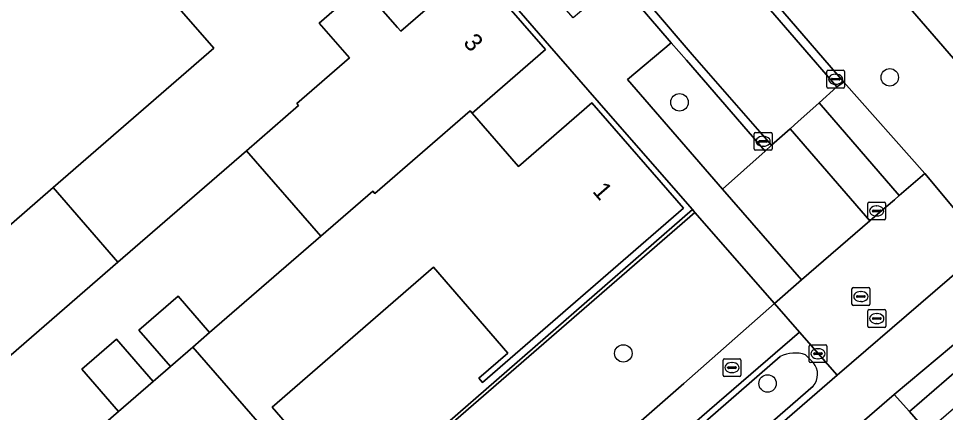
# Model space of a CAD drawing. Extents: x 155887 to 156869, y 383880 to 384678.
# Drawn here: x 156224 to 156276, y 384085.6 to 384107.7 of the extents above; entities that cross this region are included whole.
import ezdxf

# ---------------------------------------------------------------- set-up
doc = ezdxf.new("R2010")
doc.units = 0
for name, color, linetype in [('IMGEO_Berm_groen', 7, 'Continuous'), ('IMGEO_Boom', 7, 'Continuous'), ('IMGEO_Erf', 7, 'Continuous'), ('IMGEO_Fietspad_gesloten', 7, 'Continuous'), ('IMGEO_Greppel_droge_sloot', 7, 'Continuous'), ('IMGEO_Groenvoorziening', 7, 'Continuous'), ('IMGEO_Haag', 7, 'Continuous'), ('IMGEO_Kolk', 7, 'Continuous'), ('IMGEO_Pand', 7, 'Continuous'), ('IMGEO_Pand_nummerreeks', 7, 'Continuous'), ('IMGEO_Rijbaan_lokaal_gesloten', 7, 'Continuous'), ('IMGEO_Rijbaan_lokaal_open', 7, 'Continuous'), ('IMGEO_Rioolput', 7, 'Continuous'), ('IMGEO_Voetpad_open', 7, 'Continuous')]:
    doc.layers.add(name, color=color, linetype=linetype)

msp = doc.modelspace()

# ---------------------------------------------------------------- linework, layer by layer
at = {"layer": 'IMGEO_Berm_groen'}
for points in [[(156240.218, 384147.268), (156236.004, 384143.601), (156236.378, 384143.165), (156259.369, 384116.661), (156259.86, 384116.097), (156266.847, 384108.071), (156270.265, 384104.121), (156274.816, 384099.002), (156277.067, 384096.295), (156281.229, 384099.923), (156277.633, 384104.037), (156267.33, 384115.942)], [(156261.455, 384105.344), (156260.59, 384106.325), (156258.145, 384104.257), (156263.479, 384098.12), (156265.865, 384100.248)], [(156270.265, 384104.121), (156269.874, 384103.844), (156268.884, 384102.961), (156273.38, 384097.76), (156274.816, 384099.002)], [(156267.255, 384101.508), (156266.212, 384100.578), (156265.865, 384100.248), (156263.479, 384098.12), (156267.907, 384093.026), (156271.731, 384096.334)], [(156267.782, 384090.109), (156262.74, 384085.745), (156228.231, 384055.73), (156230.294, 384053.373), (156269.896, 384087.691)]]:
    msp.add_lwpolyline(points, close=True, dxfattribs=at)
for points in [[(156229.652, 384056.467), (156266.709, 384088.74)], [(156268.123, 384088.828), (156268.567, 384088.388)], [(156268.552, 384087.083), (156231.611, 384054.962)]]:
    msp.add_lwpolyline(points, dxfattribs=at)
for centre, radius, start, end in [((156267.519, 384087.133), 1.8, 70.3811, 116.7413), ((156267.799, 384087.744), 1.002, 318.7214, 39.9615)]:
    msp.add_arc(centre, radius, start, end, dxfattribs=at)
at = {"layer": 'IMGEO_Boom'}
for centre in [(156272.845, 384104.384), (156261.061, 384102.983), (156257.913, 384088.912), (156265.996, 384087.225)]:
    msp.add_circle(centre, 0.489, dxfattribs=at)
at = {"layer": 'IMGEO_Erf'}
for points in [[(156233.788, 384073.174), (156236.052, 384075.143), (156235.843, 384075.385), (156236.084, 384075.595), (156236.293, 384075.353), (156236.363, 384075.42), (156236.657, 384075.088), (156237.409, 384075.743), (156244.556, 384081.969), (156245.305, 384082.622), (156261.783, 384096.974), (156257.057, 384102.381), (156253.783, 384106.157), (156249.606, 384110.968), (156241.618, 384120.183), (156237.428, 384125.007), (156235.411, 384127.346), (156228.952, 384134.784), (156195.288, 384105.561), (156189.338, 384100.396), (156193.713, 384095.326), (156201.684, 384086.153), (156205.864, 384081.345), (156221.93, 384062.847)], [(156234.965, 384106.021), (156230.69, 384110.939), (156231.808, 384111.909), (156231.69, 384112.045), (156229.307, 384114.791), (156227.527, 384116.842), (156217.399, 384108.054), (156208.415, 384100.257), (156212.696, 384095.324), (156212.814, 384095.188), (156211.705, 384094.224), (156215.875, 384089.428), (156225.97, 384098.203)], [(156236.789, 384100.268), (156229.588, 384094.022), (156220.6, 384086.227), (156224.76, 384081.431), (156229.628, 384085.654), (156227.569, 384088.028), (156229.513, 384089.714), (156231.573, 384087.341), (156232.538, 384088.178), (156230.767, 384090.219), (156232.958, 384092.12), (156234.729, 384090.078), (156240.961, 384095.484)]]:
    msp.add_lwpolyline(points, close=True, dxfattribs=at)
msp.add_lwpolyline([(156243.249, 384109.497), (156245.253, 384107.188), (156245.439, 384106.973), (156249.554, 384110.547), (156253.551, 384105.953), (156249.439, 384102.376), (156252.039, 384099.387), (156256.151, 384102.964), (156261.293, 384097.054), (156250.026, 384087.273), (156249.817, 384087.515), (156251.448, 384088.93), (156247.275, 384093.741), (156238.225, 384085.892), (156239.798, 384084.078)], dxfattribs=at)
at = {"layer": 'IMGEO_Fietspad_gesloten'}
for points in [[(156321.213, 384132.469), (156314.047, 384125.913), (156291.359, 384106.231), (156284.254, 384100.056), (156283.954, 384099.797), (156269.896, 384087.691), (156230.294, 384053.373), (156228.715, 384051.972), (156223.252, 384047.246), (156221.532, 384045.745), (156182.003, 384011.384), (156180.455, 384010.006), (156174.916, 384005.204), (156173.353, 384003.808), (156169.034, 384000), (156168.573, 383999.541)], [(156225.091, 384044.821), (156232.142, 384050.972), (156265.486, 384080.026), (156271.299, 384085.055), (156273.092, 384086.615), (156283.541, 384095.347), (156286.027, 384097.441), (156286.341, 384097.706), (156304.975, 384114.033), (156305.378, 384113.591), (156305.662, 384113.279), (156306.714, 384114.217), (156306.4, 384114.594), (156306.05, 384115.013), (156315.997, 384123.54), (156323.254, 384130.15), (156323.467, 384130.447)]]:
    msp.add_lwpolyline(points, dxfattribs=at)
at = {"layer": 'IMGEO_Greppel_droge_sloot'}
for points in [[(156266.709, 384088.74), (156229.652, 384056.467)], [(156268.567, 384088.388), (156268.123, 384088.828)], [(156231.611, 384054.962), (156268.552, 384087.083)]]:
    msp.add_lwpolyline(points, dxfattribs=at)
for centre, radius, start, end in [((156267.519, 384087.133), 1.8, 70.3811, 116.7413), ((156267.799, 384087.744), 1.002, 318.7214, 39.9615)]:
    msp.add_arc(centre, radius, start, end, dxfattribs=at)
at = {"layer": 'IMGEO_Groenvoorziening'}
for points in [[(156245.422, 384082.489), (156261.927, 384096.809), (156261.783, 384096.974), (156245.305, 384082.622)], [(156249.95, 384077.285), (156261.303, 384087.219), (156266.381, 384091.712), (156261.927, 384096.809), (156245.422, 384082.489)], [(156280.05, 384090.968), (156280.427, 384091.296), (156284.205, 384094.584), (156283.541, 384095.347), (156273.092, 384086.615), (156273.953, 384085.664), (156276.712, 384088.043)]]:
    msp.add_lwpolyline(points, close=True, dxfattribs=at)
at = {"layer": 'IMGEO_Haag'}
for points in [[(156245.422, 384082.489), (156261.927, 384096.809), (156261.783, 384096.974), (156245.305, 384082.622)], [(156273.092, 384086.615), (156273.953, 384085.664), (156276.712, 384088.043), (156280.05, 384090.968), (156280.427, 384091.296), (156284.205, 384094.584), (156283.541, 384095.347)]]:
    msp.add_lwpolyline(points, close=True, dxfattribs=at)
at = {"layer": 'IMGEO_Kolk'}
for p, q in [((156269.312, 384103.855), (156269.312, 384104.707)), ((156269.387, 384104.781), (156270.239, 384104.781)), ((156269.614, 384104.324), (156270.012, 384104.324)), ((156269.8, 384104.561), (156269.825, 384104.561)), ((156270.313, 384104.707), (156270.313, 384103.855)), ((156269.571, 384104.275), (156269.571, 384104.287)), ((156270.009, 384104.238), (156269.611, 384104.238)), ((156269.823, 384104.001), (156269.798, 384104.001)), ((156270.055, 384104.287), (156270.055, 384104.275)), ((156270.239, 384103.781), (156269.387, 384103.781)), ((156265.247, 384100.374), (156265.247, 384101.226)), ((156265.322, 384101.3), (156266.174, 384101.3)), ((156266.248, 384101.226), (156266.248, 384100.374)), ((156265.506, 384100.794), (156265.506, 384100.806)), ((156265.944, 384100.757), (156265.546, 384100.757)), ((156265.549, 384100.843), (156265.947, 384100.843)), ((156265.735, 384101.08), (156265.76, 384101.08)), ((156265.99, 384100.806), (156265.99, 384100.794)), ((156266.174, 384100.3), (156265.322, 384100.3)), ((156265.758, 384100.52), (156265.733, 384100.52)), ((156268.322, 384088.467), (156268.322, 384089.319)), ((156268.397, 384089.393), (156269.249, 384089.393)), ((156269.323, 384089.319), (156269.323, 384088.467)), ((156268.581, 384088.887), (156268.581, 384088.899)), ((156269.019, 384088.85), (156268.621, 384088.85)), ((156268.624, 384088.936), (156269.022, 384088.936)), ((156268.81, 384089.173), (156268.835, 384089.173)), ((156269.065, 384088.899), (156269.065, 384088.887)), ((156269.249, 384088.393), (156268.397, 384088.393)), ((156268.833, 384088.613), (156268.808, 384088.613))]:
    msp.add_line(p, q, dxfattribs=at)
for points in [[(156269.312, 384103.855), (156269.312, 384104.707)], [(156269.387, 384104.781), (156270.239, 384104.781)], [(156270.313, 384104.707), (156270.313, 384103.855)], [(156270.239, 384103.781), (156269.387, 384103.781)], [(156265.247, 384100.374), (156265.247, 384101.226)], [(156265.322, 384101.3), (156266.174, 384101.3)], [(156266.248, 384101.226), (156266.248, 384100.374)], [(156266.174, 384100.3), (156265.322, 384100.3)], [(156268.322, 384088.467), (156268.322, 384089.319)], [(156268.397, 384089.393), (156269.249, 384089.393)], [(156269.323, 384089.319), (156269.323, 384088.467)], [(156269.249, 384088.393), (156268.397, 384088.393)]]:
    msp.add_lwpolyline(points, dxfattribs=at)
for centre, radius, start, end in [((156269.389, 384104.705), 0.0765, 91.552, 178.448), ((156269.389, 384104.705), 0.0765, 91.552, 178.448), ((156269.611, 384104.284), 0.0403, 85.8775, 175.7526), ((156270.016, 384104.286), 0.0386, 1.7309, 96.639), ((156270.237, 384104.705), 0.0765, 1.552, 88.448), ((156270.237, 384104.705), 0.0765, 1.552, 88.448), ((156269.389, 384103.857), 0.0765, 181.552, 268.448), ((156269.389, 384103.857), 0.0765, 181.552, 268.448), ((156269.608, 384104.274), 0.0366, 178.938, 274.7102), ((156270.012, 384104.281), 0.043, 264.8664, 352.4533), ((156270.237, 384103.857), 0.0765, 271.552, 358.448), ((156270.237, 384103.857), 0.0765, 271.552, 358.448), ((156265.324, 384101.224), 0.0765, 91.552, 178.448), ((156265.324, 384101.224), 0.0765, 91.552, 178.448), ((156266.172, 384101.224), 0.0765, 1.552, 88.448), ((156266.172, 384101.224), 0.0765, 1.552, 88.448), ((156265.546, 384100.803), 0.0403, 85.8775, 175.7526), ((156265.543, 384100.793), 0.0366, 178.938, 274.7102), ((156265.947, 384100.8), 0.043, 264.8664, 352.4533), ((156265.951, 384100.805), 0.0386, 1.7309, 96.639), ((156265.324, 384100.376), 0.0765, 181.552, 268.448), ((156265.324, 384100.376), 0.0765, 181.552, 268.448), ((156266.172, 384100.376), 0.0765, 271.552, 358.448), ((156266.172, 384100.376), 0.0765, 271.552, 358.448), ((156268.399, 384089.317), 0.0765, 91.552, 178.448), ((156268.399, 384089.317), 0.0765, 91.552, 178.448), ((156269.247, 384089.317), 0.0765, 1.552, 88.448), ((156269.247, 384089.317), 0.0765, 1.552, 88.448), ((156268.621, 384088.896), 0.0403, 85.8775, 175.7526), ((156268.618, 384088.886), 0.0366, 178.938, 274.7102), ((156269.022, 384088.893), 0.043, 264.8664, 352.4533), ((156269.026, 384088.898), 0.0386, 1.7309, 96.639), ((156268.399, 384088.469), 0.0765, 181.552, 268.448), ((156268.399, 384088.469), 0.0765, 181.552, 268.448), ((156269.247, 384088.469), 0.0765, 271.552, 358.448), ((156269.247, 384088.469), 0.0765, 271.552, 358.448)]:
    msp.add_arc(centre, radius, start, end, dxfattribs=at)
for centre, major_axis, ratio, start_param, end_param in [((156269.799, 384104.281), (-0.387, 0.002), 0.722429, 4.712389, 7.853982), ((156269.824, 384104.281), (-0.39, 0.002), 0.717154, 1.570796, 4.712389), ((156265.734, 384100.8), (-0.387, 0.002), 0.722429, 4.712389, 7.853982), ((156265.759, 384100.8), (-0.39, 0.002), 0.717154, 1.570796, 4.712389), ((156268.809, 384088.893), (-0.387, 0.002), 0.722429, 4.712389, 7.853982), ((156268.834, 384088.893), (-0.39, 0.002), 0.717154, 1.570796, 4.712389)]:
    msp.add_ellipse(centre, major_axis=major_axis, ratio=ratio, start_param=start_param, end_param=end_param, dxfattribs=at)
at = {"layer": 'IMGEO_Pand'}
for points in [[(156240.864, 384107.428), (156243.249, 384109.497), (156240.589, 384112.564), (156244.444, 384115.913), (156244.704, 384116.138), (156241.375, 384119.971), (156241.257, 384120.107), (156231.808, 384111.909), (156230.69, 384110.939), (156234.965, 384106.021), (156225.97, 384098.203), (156229.588, 384094.022), (156236.789, 384100.268), (156239.708, 384102.8), (156239.608, 384102.916), (156242.561, 384105.472)], [(156253.551, 384105.953), (156249.554, 384110.547), (156245.439, 384106.973), (156245.253, 384107.188), (156243.249, 384109.497), (156240.864, 384107.428), (156242.561, 384105.472), (156239.608, 384102.916), (156239.708, 384102.8), (156236.789, 384100.268), (156240.961, 384095.484), (156243.868, 384098.005), (156243.979, 384097.877), (156249.322, 384102.511), (156249.439, 384102.376)], [(156247.275, 384093.741), (156251.448, 384088.93), (156249.817, 384087.515), (156250.026, 384087.273), (156261.293, 384097.054), (156256.151, 384102.964), (156252.039, 384099.387), (156249.439, 384102.376), (156249.322, 384102.511), (156243.979, 384097.877), (156243.868, 384098.005), (156240.961, 384095.484), (156234.729, 384090.078), (156233.787, 384089.261), (156237.403, 384085.095), (156236.453, 384084.272), (156237.985, 384082.506), (156239.798, 384084.078), (156238.225, 384085.892)], [(156215.875, 384089.428), (156215.978, 384089.309), (156213.039, 384086.757), (156214.718, 384084.823), (156212.298, 384082.722), (156214.887, 384079.743), (156211.02, 384076.394), (156210.767, 384076.175), (156214.404, 384071.976), (156214.662, 384072.199), (156218.524, 384075.544), (156218.399, 384075.688), (156224.872, 384081.302), (156224.76, 384081.431), (156220.6, 384086.227), (156229.588, 384094.022), (156225.97, 384098.203)], [(156230.767, 384090.219), (156232.538, 384088.178), (156233.787, 384089.261), (156234.729, 384090.078), (156232.958, 384092.12)], [(156227.924, 384076.958), (156236.453, 384084.272), (156237.403, 384085.095), (156233.787, 384089.261), (156232.538, 384088.178), (156231.573, 384087.341), (156229.628, 384085.654), (156224.76, 384081.431), (156224.872, 384081.302), (156218.399, 384075.688), (156218.524, 384075.544), (156223.323, 384070.035), (156219.458, 384066.693), (156219.2, 384066.47), (156222.126, 384063.086), (156226.241, 384066.645), (156232.313, 384071.898), (156233.788, 384073.174), (156233.579, 384073.417), (156232.103, 384072.14)], [(156227.569, 384088.028), (156229.628, 384085.654), (156231.573, 384087.341), (156229.513, 384089.714)]]:
    msp.add_lwpolyline(points, close=True, dxfattribs=at)
at = {"layer": 'IMGEO_Rijbaan_lokaal_gesloten'}
msp.add_lwpolyline([(156235.655, 384143.297), (156235.555, 384143.21), (156231.878, 384140.144), (156233.823, 384137.913), (156236.835, 384134.451), (156242.248, 384128.205), (156249.071, 384120.349), (156254.436, 384114.138), (156257.926, 384110.141), (156259.428, 384108.395), (156261.774, 384105.668), (156266.212, 384100.578), (156267.255, 384101.508), (156267.705, 384101.909), (156268.531, 384102.646), (156268.884, 384102.961), (156269.874, 384103.844), (156265.798, 384108.566), (156259.022, 384116.36)], close=True, dxfattribs=at)
at = {"layer": 'IMGEO_Rijbaan_lokaal_open'}
for points in [[(156236.378, 384143.165), (156236.004, 384143.601), (156235.655, 384143.297), (156259.022, 384116.36), (156265.798, 384108.566), (156269.874, 384103.844), (156270.265, 384104.121), (156266.847, 384108.071), (156259.86, 384116.097), (156259.369, 384116.661)], [(156231.878, 384140.144), (156231.541, 384139.83), (156233.476, 384137.611), (156236.488, 384134.15), (156241.9, 384127.903), (156248.723, 384120.048), (156254.089, 384113.836), (156257.579, 384109.84), (156260.59, 384106.325), (156261.455, 384105.344), (156265.865, 384100.248), (156266.212, 384100.578), (156261.774, 384105.668), (156259.428, 384108.395), (156257.926, 384110.141), (156254.436, 384114.138), (156249.071, 384120.349), (156242.248, 384128.205), (156236.835, 384134.451), (156233.823, 384137.913)]]:
    msp.add_lwpolyline(points, close=True, dxfattribs=at)
at = {"layer": 'IMGEO_Rioolput'}
for p, q in [((156271.61, 384096.469), (156271.61, 384097.321)), ((156271.685, 384097.395), (156272.537, 384097.395)), ((156272.098, 384097.175), (156272.123, 384097.175)), ((156272.611, 384097.321), (156272.611, 384096.469)), ((156271.869, 384096.889), (156271.869, 384096.901)), ((156272.307, 384096.852), (156271.909, 384096.852)), ((156271.912, 384096.938), (156272.31, 384096.938)), ((156272.121, 384096.615), (156272.096, 384096.615)), ((156272.353, 384096.901), (156272.353, 384096.889)), ((156272.537, 384096.395), (156271.685, 384096.395)), ((156270.725, 384091.674), (156270.725, 384092.526)), ((156270.8, 384092.6), (156271.652, 384092.6)), ((156271.213, 384092.38), (156271.238, 384092.38)), ((156271.726, 384092.526), (156271.726, 384091.674)), ((156270.984, 384092.094), (156270.984, 384092.106)), ((156271.422, 384092.057), (156271.024, 384092.057)), ((156271.027, 384092.143), (156271.425, 384092.143)), ((156271.468, 384092.106), (156271.468, 384092.094)), ((156271.652, 384091.6), (156270.8, 384091.6)), ((156271.236, 384091.82), (156271.211, 384091.82)), ((156271.692, 384091.366), (156272.544, 384091.366)), ((156271.617, 384090.44), (156271.617, 384091.292)), ((156271.876, 384090.86), (156271.876, 384090.872)), ((156272.314, 384090.823), (156271.916, 384090.823)), ((156271.919, 384090.909), (156272.317, 384090.909)), ((156272.105, 384091.146), (156272.13, 384091.146)), ((156272.36, 384090.872), (156272.36, 384090.86)), ((156272.618, 384091.292), (156272.618, 384090.44)), ((156272.544, 384090.366), (156271.692, 384090.366)), ((156272.128, 384090.586), (156272.103, 384090.586)), ((156263.501, 384087.688), (156263.501, 384088.54)), ((156263.576, 384088.614), (156264.428, 384088.614)), ((156263.989, 384088.394), (156264.014, 384088.394)), ((156264.502, 384088.54), (156264.502, 384087.688)), ((156263.76, 384088.108), (156263.76, 384088.12)), ((156264.198, 384088.071), (156263.8, 384088.071)), ((156263.803, 384088.157), (156264.201, 384088.157)), ((156264.012, 384087.834), (156263.987, 384087.834)), ((156264.244, 384088.12), (156264.244, 384088.108)), ((156264.428, 384087.614), (156263.576, 384087.614))]:
    msp.add_line(p, q, dxfattribs=at)
for points in [[(156271.61, 384096.469), (156271.61, 384097.321)], [(156271.685, 384097.395), (156272.537, 384097.395)], [(156272.611, 384097.321), (156272.611, 384096.469)], [(156272.537, 384096.395), (156271.685, 384096.395)], [(156270.725, 384091.674), (156270.725, 384092.526)], [(156270.8, 384092.6), (156271.652, 384092.6)], [(156271.726, 384092.526), (156271.726, 384091.674)], [(156271.652, 384091.6), (156270.8, 384091.6)], [(156271.692, 384091.366), (156272.544, 384091.366)], [(156271.617, 384090.44), (156271.617, 384091.292)], [(156272.618, 384091.292), (156272.618, 384090.44)], [(156272.544, 384090.366), (156271.692, 384090.366)], [(156263.501, 384087.688), (156263.501, 384088.54)], [(156263.576, 384088.614), (156264.428, 384088.614)], [(156264.502, 384088.54), (156264.502, 384087.688)], [(156264.428, 384087.614), (156263.576, 384087.614)]]:
    msp.add_lwpolyline(points, dxfattribs=at)
for centre, radius, start, end in [((156271.687, 384097.319), 0.0765, 91.552, 178.448), ((156271.687, 384097.319), 0.0765, 91.552, 178.448), ((156272.535, 384097.319), 0.0765, 1.552, 88.448), ((156272.535, 384097.319), 0.0765, 1.552, 88.448), ((156271.909, 384096.898), 0.0403, 85.8775, 175.7526), ((156271.906, 384096.888), 0.0366, 178.938, 274.7102), ((156272.31, 384096.895), 0.043, 264.8664, 352.4533), ((156272.314, 384096.9), 0.0386, 1.7309, 96.639), ((156271.687, 384096.471), 0.0765, 181.552, 268.448), ((156271.687, 384096.471), 0.0765, 181.552, 268.448), ((156272.535, 384096.471), 0.0765, 271.552, 358.448), ((156272.535, 384096.471), 0.0765, 271.552, 358.448), ((156270.802, 384092.524), 0.0765, 91.552, 178.448), ((156270.802, 384092.524), 0.0765, 91.552, 178.448), ((156271.65, 384092.524), 0.0765, 1.552, 88.448), ((156271.65, 384092.524), 0.0765, 1.552, 88.448), ((156271.024, 384092.103), 0.0403, 85.8775, 175.7526), ((156271.021, 384092.093), 0.0366, 178.938, 274.7102), ((156271.425, 384092.1), 0.043, 264.8664, 352.4533), ((156271.429, 384092.105), 0.0386, 1.7309, 96.639), ((156270.802, 384091.676), 0.0765, 181.552, 268.448), ((156270.802, 384091.676), 0.0765, 181.552, 268.448), ((156271.694, 384091.29), 0.0765, 91.552, 178.448), ((156271.694, 384091.29), 0.0765, 91.552, 178.448), ((156271.65, 384091.676), 0.0765, 271.552, 358.448), ((156271.65, 384091.676), 0.0765, 271.552, 358.448), ((156272.542, 384091.29), 0.0765, 1.552, 88.448), ((156272.542, 384091.29), 0.0765, 1.552, 88.448), ((156271.916, 384090.869), 0.0403, 85.8775, 175.7526), ((156271.913, 384090.859), 0.0366, 178.938, 274.7102), ((156272.317, 384090.866), 0.043, 264.8664, 352.4533), ((156272.321, 384090.871), 0.0386, 1.7309, 96.639), ((156271.694, 384090.442), 0.0765, 181.552, 268.448), ((156271.694, 384090.442), 0.0765, 181.552, 268.448), ((156272.542, 384090.442), 0.0765, 271.552, 358.448), ((156272.542, 384090.442), 0.0765, 271.552, 358.448), ((156263.578, 384088.538), 0.0765, 91.552, 178.448), ((156263.578, 384088.538), 0.0765, 91.552, 178.448), ((156264.426, 384088.538), 0.0765, 1.552, 88.448), ((156264.426, 384088.538), 0.0765, 1.552, 88.448), ((156263.578, 384087.69), 0.0765, 181.552, 268.448), ((156263.578, 384087.69), 0.0765, 181.552, 268.448), ((156263.8, 384088.117), 0.0403, 85.8775, 175.7526), ((156263.797, 384088.107), 0.0366, 178.938, 274.7102), ((156264.201, 384088.114), 0.043, 264.8664, 352.4533), ((156264.205, 384088.119), 0.0386, 1.7309, 96.639), ((156264.426, 384087.69), 0.0765, 271.552, 358.448), ((156264.426, 384087.69), 0.0765, 271.552, 358.448)]:
    msp.add_arc(centre, radius, start, end, dxfattribs=at)
for centre, major_axis, ratio, start_param, end_param in [((156272.097, 384096.895), (-0.387, 0.002), 0.722429, 4.712389, 7.853982), ((156272.122, 384096.895), (-0.39, 0.002), 0.717154, 1.570796, 4.712389), ((156271.212, 384092.1), (-0.387, 0.002), 0.722429, 4.712389, 7.853982), ((156271.237, 384092.1), (-0.39, 0.002), 0.717154, 1.570796, 4.712389), ((156272.104, 384090.866), (-0.387, 0.002), 0.722429, 4.712389, 7.853982), ((156272.129, 384090.866), (-0.39, 0.002), 0.717154, 1.570796, 4.712389), ((156263.988, 384088.114), (-0.387, 0.002), 0.722429, 4.712389, 7.853982), ((156264.013, 384088.114), (-0.39, 0.002), 0.717154, 1.570796, 4.712389)]:
    msp.add_ellipse(centre, major_axis=major_axis, ratio=ratio, start_param=start_param, end_param=end_param, dxfattribs=at)
at = {"layer": 'IMGEO_Voetpad_open'}
for points in [[(156242.753, 384147.346), (156241.709, 384148.549), (156240.218, 384147.268), (156267.33, 384115.942), (156277.633, 384104.037), (156281.229, 384099.923), (156282.76, 384101.221), (156279.529, 384104.91), (156267.335, 384118.935), (156266.876, 384119.462), (156265.908, 384120.63), (156262.942, 384124.079), (156261.085, 384126.207), (156259.179, 384128.391), (156256.203, 384131.83), (156252.45, 384136.162), (156249.466, 384139.578), (156247.639, 384141.692), (156245.72, 384143.913)], [(156283.954, 384099.797), (156284.254, 384100.056), (156291.359, 384106.231), (156290.137, 384107.648), (156282.76, 384101.221), (156281.229, 384099.923), (156277.067, 384096.295), (156274.816, 384099.002), (156273.38, 384097.76), (156273.102, 384097.52), (156272.292, 384096.819), (156271.731, 384096.334), (156267.907, 384093.026), (156266.381, 384091.712), (156267.782, 384090.109), (156269.896, 384087.691)], [(156268.884, 384102.961), (156268.531, 384102.646), (156267.705, 384101.909), (156267.255, 384101.508), (156271.731, 384096.334), (156272.292, 384096.819), (156273.102, 384097.52), (156273.38, 384097.76)], [(156302.817, 384058.029), (156285.623, 384077.838), (156276.712, 384088.043), (156273.953, 384085.664), (156274.92, 384084.542), (156277.086, 384086.398), (156306.425, 384052.676), (156306.981, 384053.222)]]:
    msp.add_lwpolyline(points, close=True, dxfattribs=at)
for points in [[(156225.054, 384139.316), (156227.956, 384135.922), (156228.952, 384134.784), (156235.411, 384127.346), (156237.428, 384125.007), (156241.618, 384120.183), (156249.606, 384110.968), (156253.783, 384106.157), (156257.057, 384102.381), (156261.783, 384096.974), (156261.927, 384096.809), (156266.381, 384091.712), (156267.907, 384093.026), (156263.479, 384098.12), (156258.145, 384104.257), (156260.59, 384106.325), (156257.579, 384109.84), (156255.109, 384107.715), (156251.641, 384111.7), (156254.089, 384113.836), (156248.723, 384120.048)], [(156221.196, 384049.632), (156226.604, 384054.357), (156228.715, 384051.972), (156230.294, 384053.373), (156228.231, 384055.73), (156262.74, 384085.745), (156267.782, 384090.109), (156266.381, 384091.712), (156261.303, 384087.219), (156249.95, 384077.285), (156249.17, 384076.616), (156241.981, 384070.342), (156241.203, 384069.676), (156226.832, 384057.225), (156225.312, 384055.892), (156219.734, 384051.063)], [(156307.48, 384046.967), (156304.211, 384050.794), (156274.92, 384084.542), (156273.953, 384085.664), (156273.092, 384086.615), (156271.299, 384085.055), (156271.983, 384084.296), (156268.833, 384081.577), (156269.034, 384081.375), (156271.154, 384079.254), (156271.41, 384079.469), (156271.716, 384079.723), (156276.904, 384073.775), (156277.17, 384073.469), (156279.774, 384075.773), (156291.285, 384062.581), (156288.058, 384059.795), (156291.525, 384055.794), (156292.746, 384054.384), (156299.309, 384046.811)]]:
    msp.add_lwpolyline(points, dxfattribs=at)

# ---------------------------------------------------------------- texts
at = {"layer": 'IMGEO_Pand_nummerreeks'}
for s, p in [('3', (156248.898, 384106.304)), ('1', (156256.141, 384097.977))]:
    msp.add_text(s, height=1, rotation=311.0236, dxfattribs=at).set_placement(p)

doc.saveas('drawing.dxf')
